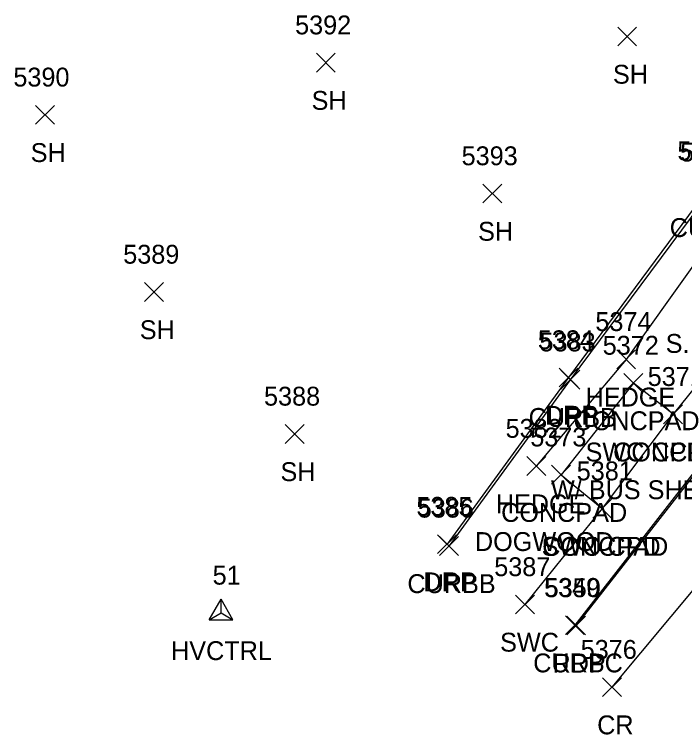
# Model space of a CAD drawing. Extents: x 1618146 to 1620418, y 640749 to 641927.
# Drawn here: x 1620148.3 to 1620219.4, y 640886.9 to 640963.2 of the extents above; entities that cross this region are included whole.
import ezdxf

# ---------------------------------------------------------------- set-up
doc = ezdxf.new("R2010")
doc.units = 0
for name, color, linetype in [('C_A', 7, 'Continuous'), ('C_I', 7, 'Continuous'), ('CPSM', 7, 'Continuous'), ('L_A', 7, 'Continuous'), ('L_C', 7, 'Continuous'), ('L_I', 7, 'Continuous'), ('L_TIC', 7, 'Continuous'), ('LAHR', 7, 'Continuous'), ('LS', 7, 'Continuous'), ('P_A', 7, 'Continuous'), ('P_I', 7, 'Continuous'), ('P_TIC', 7, 'Continuous'), ('PET', 7, 'Continuous'), ('PRC', 7, 'Continuous'), ('R_A', 7, 'Continuous'), ('R_C', 7, 'Continuous'), ('R_I', 7, 'Continuous'), ('R_TIC', 7, 'Continuous'), ('RC', 7, 'Continuous'), ('RDP', 7, 'Continuous'), ('RSW', 7, 'Continuous')]:
    doc.layers.add(name, color=color, linetype=linetype)

msp = doc.modelspace()

# ---------------------------------------------------------------- linework, layer by layer
at = {"layer": 'CPSM'}
for p, q in [((1620169.006, 640899.028), (1620170.256, 640901.193)), ((1620171.506, 640899.028), (1620170.256, 640901.193)), ((1620170.256, 640899.749), (1620170.256, 640901.193)), ((1620169.006, 640899.028), (1620170.256, 640899.749)), ((1620170.256, 640899.749), (1620170.256, 640899.749)), ((1620170.256, 640899.749), (1620171.506, 640899.028)), ((1620169.006, 640899.028), (1620171.506, 640899.028))]:
    msp.add_line(p, q, dxfattribs=at)
at = {"layer": 'L_TIC'}
for points in [[(1620212.333, 640959.846), (1620214.333, 640961.846)], [(1620214.333, 640959.846), (1620212.333, 640961.846)], [(1620180.367, 640957.075), (1620182.367, 640959.075)], [(1620182.367, 640957.075), (1620180.367, 640959.075)], [(1620150.57, 640951.544), (1620152.57, 640953.544)], [(1620152.57, 640951.544), (1620150.57, 640953.544)], [(1620198.029, 640943.201), (1620200.029, 640945.201)], [(1620200.029, 640943.201), (1620198.029, 640945.201)], [(1620162.144, 640932.768), (1620164.144, 640934.768)], [(1620164.144, 640932.768), (1620162.144, 640934.768)], [(1620212.218, 640925.628), (1620214.218, 640927.628)], [(1620214.218, 640925.628), (1620212.218, 640927.628)], [(1620212.994, 640923.119), (1620214.994, 640925.119)], [(1620214.994, 640923.119), (1620212.994, 640925.119)], [(1620217.2, 640919.806), (1620219.2, 640921.806)], [(1620219.2, 640919.806), (1620217.2, 640921.806)], [(1620177.07, 640917.722), (1620179.07, 640919.722)], [(1620179.07, 640917.722), (1620177.07, 640919.722)], [(1620202.694, 640914.312), (1620204.694, 640916.312)], [(1620204.694, 640914.312), (1620202.694, 640916.312)], [(1620205.314, 640913.398), (1620207.314, 640915.398)], [(1620207.314, 640913.398), (1620205.314, 640915.398)], [(1620209.672, 640909.804), (1620211.672, 640911.804)], [(1620211.672, 640909.804), (1620209.672, 640911.804)]]:
    msp.add_lwpolyline(points, dxfattribs=at)
at = {"layer": 'LAHR'}
msp.add_lwpolyline([(1620227.694, 640946.866), (1620213.218, 640926.628), (1620203.694, 640915.312)], dxfattribs=at)
at = {"layer": 'LS'}
msp.add_lwpolyline([(1620218.2, 640920.806), (1620213.994, 640924.119), (1620206.314, 640914.398), (1620210.672, 640910.804)], dxfattribs=at)
at = {"layer": 'P_TIC'}
for points in [[(1620206.924, 640897.413), (1620208.924, 640899.413)], [(1620208.924, 640897.413), (1620206.924, 640899.413)], [(1620210.715, 640890.88), (1620212.715, 640892.88)], [(1620212.715, 640890.88), (1620210.715, 640892.88)]]:
    msp.add_lwpolyline(points, dxfattribs=at)
at = {"layer": 'PET'}
msp.add_lwpolyline([(1620359.618, 641102.741), (1620357.552, 641099.276), (1620341.731, 641075.022), (1620339.541, 641071.666), (1620329.909, 641058.991), (1620323.975, 641051.239), (1620317.974, 641043.478), (1620299.64, 641019.571), (1620282.799, 640996.951), (1620281.456, 640995.25), (1620278.195, 640990.782), (1620276.89, 640989.311), (1620275.826, 640987.688), (1620269.888, 640979.335), (1620267.257, 640975.908), (1620246.8, 640948.475), (1620237.104, 640935.681), (1620207.924, 640898.413)], dxfattribs=at)
at = {"layer": 'PRC'}
msp.add_lwpolyline([(1620362.761, 641090.181), (1620340.683, 641059.759), (1620325.328, 641039.403), (1620305.343, 641012.417), (1620285.981, 640987.098), (1620282.921, 640982.142), (1620262.646, 640955.357), (1620239.617, 640925.265), (1620211.715, 640891.88)], dxfattribs=at)
at = {"layer": 'R_TIC'}
for points in [[(1620206.113, 640923.702), (1620208.113, 640925.702)], [(1620208.113, 640923.702), (1620206.113, 640925.702)], [(1620206.295, 640923.468), (1620208.295, 640925.468)], [(1620208.295, 640923.468), (1620206.295, 640925.468)], [(1620217.2, 640919.806), (1620219.2, 640921.806)], [(1620219.2, 640919.806), (1620217.2, 640921.806)], [(1620209.672, 640909.804), (1620211.672, 640911.804)], [(1620211.672, 640909.804), (1620209.672, 640911.804)], [(1620193.229, 640906.042), (1620195.229, 640908.042)], [(1620195.229, 640906.042), (1620193.229, 640908.042)], [(1620193.434, 640905.852), (1620195.434, 640907.852)], [(1620195.434, 640905.852), (1620193.434, 640907.852)], [(1620201.49, 640899.646), (1620203.49, 640901.646)], [(1620203.49, 640899.646), (1620201.49, 640901.646)], [(1620206.783, 640897.448), (1620208.783, 640899.448)], [(1620208.783, 640897.448), (1620206.783, 640899.448)]]:
    msp.add_lwpolyline(points, dxfattribs=at)
at = {"layer": 'RC'}
for points in [[(1620241.442, 640950.866), (1620241.697, 640954.632), (1620235.897, 640957.364), (1620229.329, 640953.868), (1620222.262, 640944.594), (1620207.295, 640924.468), (1620194.434, 640906.852)], [(1620246.343, 640948.761), (1620246.8, 640948.475), (1620236.82, 640935.733), (1620207.783, 640898.448)]]:
    msp.add_lwpolyline(points, dxfattribs=at)
at = {"layer": 'RDP'}
msp.add_lwpolyline([(1620241.442, 640950.866), (1620242.306, 640954.562), (1620235.947, 640957.684), (1620233.64, 640957.473), (1620229.014, 640954.121), (1620221.966, 640944.726), (1620207.113, 640924.702), (1620194.229, 640907.042)], dxfattribs=at)
at = {"layer": 'RSW'}
msp.add_lwpolyline([(1620273.827, 640994.382), (1620271.861, 640991.557), (1620269.183, 640988.021), (1620264.777, 640981.848), (1620262.749, 640979.054), (1620260.968, 640976.582), (1620252.715, 640965.558), (1620241.442, 640950.866), (1620232.883, 640938.96), (1620218.2, 640920.806), (1620210.672, 640910.804), (1620202.49, 640900.646)], dxfattribs=at)

# ---------------------------------------------------------------- texts
at = {"layer": 'C_A'}
msp.add_text('HVCTRL', height=2, dxfattribs=at).set_placement((1620164.949, 640894.749))
at = {"layer": 'C_I'}
msp.add_text('51', height=2, dxfattribs=at).set_placement((1620169.358, 640902.749))
at = {"layer": 'L_A'}
for s, p in [('SH', (1620211.822, 640955.846)), ('SH', (1620179.855, 640953.075)), ('SH', (1620150.058, 640947.544)), ('SH', (1620197.517, 640939.201)), ('SH', (1620161.632, 640928.768)), ('HEDGE', (1620208.919, 640921.628)), ('CONCPAD', (1620207.64, 640919.119)), ('CONCPAD', (1620211.845, 640915.806)), ('SH', (1620176.558, 640913.722)), ('HEDGE', (1620199.395, 640910.312)), ('CONCPAD', (1620199.96, 640909.398)), ('CONCPAD', (1620204.317, 640905.804))]:
    msp.add_text(s, height=2, dxfattribs=at).set_placement(p)
at = {"layer": 'L_C'}
for s, p in [('S. MAPLE', (1620217.415, 640927.312)), ('DOGWOOD', (1620197.183, 640906.312))]:
    msp.add_text(s, height=2, dxfattribs=at).set_placement(p)
at = {"layer": 'L_I'}
for s, p in [('5392', (1620178.107, 640961.075)), ('5390', (1620148.223, 640955.544)), ('5393', (1620195.769, 640947.201)), ('5389', (1620159.876, 640936.768)), ('5374', (1620209.958, 640929.628)), ('5372', (1620210.735, 640927.119)), ('5371', (1620215.507, 640923.806)), ('5388', (1620174.81, 640921.722)), ('5382', (1620200.435, 640918.312)), ('5373', (1620203.054, 640917.398)), ('5381', (1620207.979, 640913.804))]:
    msp.add_text(s, height=2, dxfattribs=at).set_placement(p)
at = {"layer": 'P_A'}
for s, p in [('RDP', (1620205.412, 640893.413)), ('CR', (1620210.149, 640886.88))]:
    msp.add_text(s, height=2, dxfattribs=at).set_placement(p)
at = {"layer": 'P_I'}
for s, p in [('5350', (1620204.577, 640901.413)), ('5376', (1620208.401, 640894.88))]:
    msp.add_text(s, height=2, dxfattribs=at).set_placement(p)
at = {"layer": 'R_A'}
for s, p in [('CURBB', (1620217.845, 640939.594)), ('CURBB', (1620202.877, 640919.468)), ('DRP', (1620204.601, 640919.702)), ('SWC CPD ST', (1620208.916, 640915.806)), ('SWC CPD', (1620204.254, 640905.804)), ('CURBB', (1620190.017, 640901.852)), ('DRP', (1620191.717, 640902.042)), ('SWC', (1620199.852, 640895.646)), ('CURBC', (1620203.365, 640893.448))]:
    msp.add_text(s, height=2, dxfattribs=at).set_placement(p)
at = {"layer": 'R_C'}
msp.add_text('W/ BUS SHELTER', height=2, dxfattribs=at).set_placement((1620205.247, 640911.806))
at = {"layer": 'R_I'}
for s, p in [('5368', (1620218.659, 640947.726)), ('5367', (1620218.955, 640947.594)), ('5384', (1620203.853, 640927.702)), ('5383', (1620204.035, 640927.468)), ('5371', (1620215.507, 640923.806)), ('5381', (1620207.979, 640913.804)), ('5385', (1620190.969, 640910.042)), ('5386', (1620191.119, 640909.852)), ('5387', (1620199.23, 640903.646)), ('5349', (1620204.515, 640901.448))]:
    msp.add_text(s, height=2, dxfattribs=at).set_placement(p)

doc.saveas('drawing.dxf')
